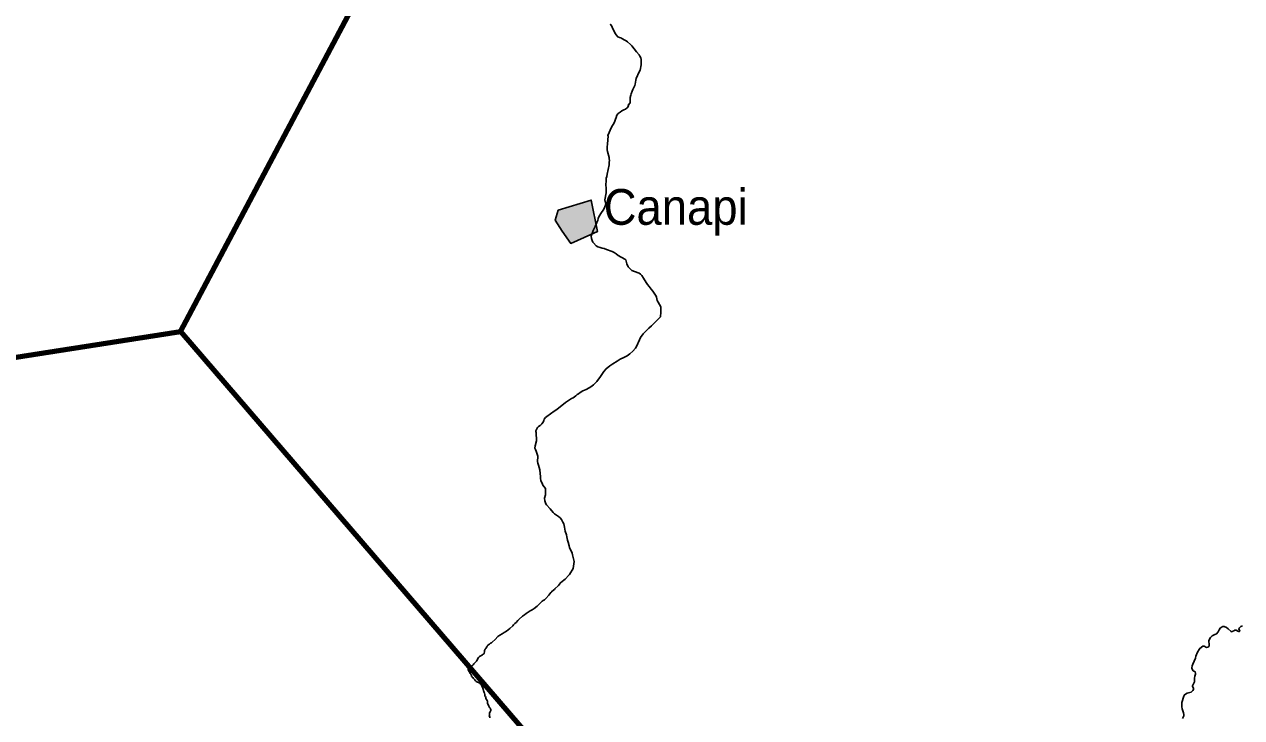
# Model space of a CAD drawing. Extents: x -1643653 to 4543381, y 1624270 to 13878484.
# Drawn here: x 644975 to 662004, y 8985110 to 8994810 of the extents above; entities that cross this region are included whole.
import ezdxf

# ---------------------------------------------------------------- set-up
doc = ezdxf.new("R2010")
doc.units = 0
doc.header["$LTSCALE"] = 200
for name, color, linetype, lineweight in [('21', 7, 'Continuous', 25), ('24', 7, 'Continuous', 25), ('60', 7, 'Continuous', 13), ('9', 7, 'Continuous', 90)]:
    doc.layers.add(name, color=color, linetype=linetype, lineweight=lineweight)
doc.layers.add('41', color=7, linetype='Continuous')

msp = doc.modelspace()

# ---------------------------------------------------------------- hatches: boundary and pattern name
at = {"layer": '21'}
msp.add_hatch(color=256, dxfattribs=at).paths.add_polyline_path([(652442.2, 8992209.7), (652905.2, 8992350.1), (652993.5, 8991912.7), (652618.8, 8991744.3), (652496.7, 8991914.1), (652399.6, 8992070.3)])

# ---------------------------------------------------------------- linework, layer by layer
msp.add_lwpolyline([(652442.2, 8992209.7), (652905.2, 8992350.1), (652993.5, 8991912.7), (652618.8, 8991744.3), (652496.7, 8991914.1), (652399.6, 8992070.3)], close=True, dxfattribs=at)
at = {"layer": '24'}
msp.add_line((651186.2, 8985771.9), (651204.8, 8985743), dxfattribs=at)
for points in [[(653170.7, 8994809.8), (653175.5, 8994807.6), (653191.3, 8994784), (653196.5, 8994768.7), (653211.1, 8994737.3), (653243.9, 8994674.7), (653252.4, 8994660.6), (653276.2, 8994633.6), (653299.1, 8994625.2), (653319.2, 8994620.5), (653334.8, 8994613.7), (653376.3, 8994588.9), (653394.7, 8994579.6), (653411.9, 8994563.4), (653455, 8994528.4), (653472.3, 8994508.8), (653537, 8994423.4), (653575.4, 8994381.7)], [(653575.4, 8994381.7), (653586.1, 8994365.1), (653599.4, 8994339.1), (653603.8, 8994319.8), (653604.9, 8994300.6), (653603.7, 8994242.8), (653588.1, 8994167.4), (653576.4, 8994144.9), (653533.3, 8994050.1), (653528, 8994030.9), (653518.3, 8993973.9), (653513.3, 8993955.5), (653488.2, 8993896.1), (653478.4, 8993876), (653466.1, 8993839), (653461.5, 8993819), (653450.8, 8993784.2), (653449.9, 8993778), (653451.5, 8993712.6), (653424.2, 8993677.3), (653424.4, 8993666.2), (653409.3, 8993643), (653384.1, 8993623.8), (653360.3, 8993615.7), (653334.2, 8993599.6), (653308, 8993581.4), (653282.8, 8993560), (653264.2, 8993540.2), (653251.9, 8993507.8), (653244.3, 8993482.9), (653237.7, 8993455.1), (653227.3, 8993430.2), (653188.7, 8993371.5), (653138.5, 8993253.8), (653138.8, 8993251.9), (653143, 8993247.7), (653131.9, 8993133.2)], [(653131.9, 8993133.2), (653129.8, 8993095.5), (653129.8, 8993054.8), (653132.2, 8993032.7), (653154.1, 8992948.6), (653155.5, 8992926.4), (653159.5, 8992905), (653155.4, 8992882), (653154.2, 8992844.1), (653130, 8992712), (653121.3, 8992682.4), (653116.5, 8992659.7), (653112.8, 8992631.9), (653112.8, 8992631.9), (653114.6, 8992605.4), (653111.6, 8992579.7), (653110.6, 8992554.8), (653113.8, 8992526.5), (653114.7, 8992476.9), (653112.5, 8992450.4), (653097.3, 8992353.7), (653111.6, 8992293.5), (653103.8, 8992279.2), (653085.8, 8992232.9), (653072.4, 8992208), (653050.1, 8992176.5), (653018, 8992124.4), (653004.3, 8992095.5), (652995.7, 8992065.1), (652985.9, 8992037.3), (652960.2, 8991981.7), (652933.3, 8991927.6), (652922.2, 8991899), (652906.4, 8991844.2), (652907.4, 8991815.5), (652917.9, 8991785.6), (652928.3, 8991762.9), (652936.6, 8991754.8), (652972.6, 8991709.8), (652998, 8991697.6), (653032.3, 8991688.1), (653060.2, 8991678.6), (653088, 8991673), (653117.6, 8991659.7), (653200.1, 8991632), (653227.9, 8991617), (653254.2, 8991600.8), (653281.5, 8991577.5), (653374.7, 8991524.4), (653387.3, 8991514.2), (653395.1, 8991496.5), (653404.1, 8991457.2), (653422.9, 8991419.4), (653438.6, 8991399.9), (653475.1, 8991367.3), (653508.4, 8991350.8), (653576.3, 8991330.8), (653594.5, 8991314.9), (653612.9, 8991293.9), (653637.5, 8991258.2), (653673.5, 8991199.1), (653693.7, 8991170.7), (653717.8, 8991140.5), (653744.1, 8991102.8), (653767.6, 8991074.9)], [(653767.6, 8991074.9), (653795.9, 8991037.1), (653814.2, 8991005.1), (653819.1, 8990993.8), (653828.8, 8990946.5), (653839.4, 8990921.2), (653878.5, 8990856.4), (653879.2, 8990781.4), (653873.4, 8990717.3), (653871, 8990712.8), (653853.9, 8990697.7), (653837.6, 8990680.5), (653785.8, 8990630.7), (653750.5, 8990593.4), (653711.8, 8990560), (653662.3, 8990513.6), (653630.7, 8990479.8), (653595.3, 8990428), (653578.7, 8990397.2), (653540.2, 8990301.5), (653523.5, 8990277.3), (653486.5, 8990235.3), (653446.5, 8990200.6), (653425.8, 8990184.6), (653406.2, 8990172.3), (653360.6, 8990147.5), (653312, 8990125.2), (653268.2, 8990099.5), (653207.5, 8990058.7), (653167.3, 8990033.5), (653113.8, 8989990.5), (653082.7, 8989954.3), (653036.6, 8989884.2), (652982.6, 8989813.8), (652936.7, 8989764.3), (652918.9, 8989751.1), (652899.7, 8989740.2)], [(652899.7, 8989740.2), (652877.8, 8989724.6), (652836.2, 8989703.3), (652811.9, 8989693.2), (652790, 8989682.3), (652749.2, 8989657.7), (652728.4, 8989641.9), (652709.2, 8989630), (652689.8, 8989614.1), (652651, 8989586.8), (652630, 8989575.5), (652587.2, 8989548.7), (652545.8, 8989519.3), (652446.2, 8989438), (652446.2, 8989438), (652410.2, 8989412.3), (652385.6, 8989397.2), (652285, 8989325.6), (652267.2, 8989307.9), (652248.4, 8989284.7), (652242.1, 8989265.4), (652232.1, 8989243.5), (652215.8, 8989220.3), (652206.6, 8989210.3), (652200.3, 8989208.7), (652190.4, 8989198.3), (652168.8, 8989181.8), (652154.9, 8989167.7), (652143.1, 8989149.5), (652131.2, 8989121), (652131.3, 8989114.2), (652134.5, 8989097.5), (652135.6, 8989052.2), (652139.7, 8989027.8), (652138.8, 8988983.3), (652120.9, 8988912.6), (652118.5, 8988880.4), (652123.9, 8988863.8), (652137.1, 8988840.6), (652156.5, 8988767.1), (652156.8, 8988741.8), (652151.8, 8988718.2), (652153.8, 8988694.7), (652158.1, 8988671.2), (652167.3, 8988644.8), (652184.8, 8988576.2), (652192.3, 8988528.1), (652195.3, 8988482.8), (652193.6, 8988458.5), (652201.4, 8988423.1), (652217.2, 8988390.3), (652226.7, 8988365.1), (652264.8, 8988314.8), (652267, 8988246.6), (652264.4, 8988229.4), (652253.4, 8988181), (652254.7, 8988143.9), (652270.8, 8988101.7), (652281, 8988087), (652329, 8988030.6), (652374.2, 8987979.9), (652391.1, 8987963.9), (652449.4, 8987924.6), (652469.8, 8987905.5), (652490.7, 8987881.2)], [(652490.7, 8987881.2), (652510.2, 8987846.4), (652519.9, 8987822.7), (652531.8, 8987775.1), (652540.2, 8987720.8), (652559.2, 8987669.4), (652563, 8987642), (652575.2, 8987593.2), (652584.9, 8987566.7), (652594.7, 8987515.3), (652603.6, 8987488.8), (652636.3, 8987409.7), (652643.8, 8987386.9), (652663.7, 8987311.6), (652665.1, 8987293.7), (652652.1, 8987197.7), (652601.8, 8987114.5), (652592.4, 8987105.1), (652542, 8987045.6), (652523, 8987034.7), (652498.3, 8987014.5), (652473.8, 8986997.1), (652445.6, 8986961.2), (652394.6, 8986912.1), (652389.2, 8986902.9), (652383.7, 8986900.8), (652349.6, 8986870.9), (652341.4, 8986859.7), (652310.3, 8986826.2), (652270.8, 8986778.6), (652249.9, 8986759.8), (652233.3, 8986751.7), (652218.9, 8986741.6), (652147.1, 8986669.5), (652105.7, 8986637.3), (652080.2, 8986619.2), (652052.1, 8986604.5)], [(652052.1, 8986604.5), (651993.9, 8986569.6), (651971.7, 8986550), (651946.1, 8986530.7), (651898, 8986488.9), (651877.6, 8986468.5), (651854.5, 8986442.5), (651837.6, 8986428.4), (651828.3, 8986417.3), (651817.8, 8986407.5), (651807.8, 8986394.7), (651766.1, 8986356.4), (651718, 8986321.2), (651688.2, 8986303.1), (651658.1, 8986282.5), (651658.1, 8986282.5), (651626.9, 8986265.4), (651599.8, 8986244.4), (651559.2, 8986206.1), (651520.7, 8986168.7)], [(661653.3, 8986283), (661653.3, 8986283), (661620.5, 8986267.7), (661592, 8986257.3), (661570, 8986232.2), (661542.9, 8986189), (661542.8, 8986172), (661548.9, 8986142.3), (661547.8, 8986116.5), (661542.4, 8986103.6), (661531.7, 8986095.3), (661511.3, 8986093.1), (661479.9, 8986111.5), (661462.2, 8986110.9), (661419.1, 8986079.2), (661409.3, 8986062.1), (661386.5, 8986028.5), (661363.9, 8985972.9), (661356, 8985944.3), (661319.8, 8985860.8), (661311.5, 8985833.8), (661305.7, 8985809), (661306.3, 8985803.2), (661316.7, 8985781.1), (661327.7, 8985766.6), (661351.7, 8985752.2), (661358.2, 8985733.2), (661356.2, 8985718.2), (661347.7, 8985689.5), (661343.3, 8985662.6), (661343.6, 8985612.7)], [(662016, 8986395.1), (661990.2, 8986386.8), (661968.5, 8986362.9), (661965.9, 8986353.2), (661971.2, 8986340.5), (661976, 8986334.1), (661975.9, 8986320.3), (661973.7, 8986317.5), (661968.6, 8986315), (661965.1, 8986315.2), (661950.7, 8986320.2), (661928.6, 8986334), (661912.3, 8986334.6), (661908.3, 8986333.7), (661893.5, 8986325.1), (661868.8, 8986314.5), (661859.1, 8986312.5), (661855.5, 8986314.2), (661815.1, 8986355.3), (661789.5, 8986371.6), (661760.9, 8986383.6), (661736.2, 8986383.9), (661731.5, 8986382.7), (661704.9, 8986363.8), (661689.3, 8986338.9), (661676.2, 8986309.1), (661653.3, 8986283)], [(651204.8, 8985743), (651207.2, 8985742), (651213.9, 8985728.9), (651219, 8985719.6), (651225.9, 8985710.1), (651228.7, 8985698.9), (651231.6, 8985688.2), (651238.7, 8985680.4), (651248, 8985669.9), (651257.4, 8985658.1), (651266.1, 8985646.8), (651274.7, 8985637.3), (651284.4, 8985627.7), (651295.8, 8985618.2), (651307, 8985610.1), (651316.5, 8985606.3), (651327.3, 8985603.1), (651336.7, 8985597), (651346.2, 8985589.2)], [(651346.2, 8985589.2), (651355, 8985581.5), (651363.6, 8985574.6), (651369.8, 8985565.8), (651376.3, 8985552.9), (651383.5, 8985538), (651388.5, 8985524.6), (651391.5, 8985509.8), (651393.7, 8985506.2), (651397.1, 8985496.6), (651400.3, 8985487), (651404.2, 8985474.3), (651408.3, 8985463), (651412.8, 8985452), (651418.7, 8985435.8), (651418.7, 8985424.8), (651417.8, 8985411.7), (651427.1, 8985404.6), (651431.1, 8985391.7), (651431, 8985378.3), (651438, 8985363.9), (651450, 8985349.8), (651452.6, 8985339), (651452.4, 8985326.2), (651455.9, 8985310.8), (651460.7, 8985300.5), (651467.1, 8985286.4), (651471.5, 8985272.6), (651480.6, 8985252), (651491.6, 8985241.3), (651498, 8985232.2), (651499.2, 8985221.1), (651498.6, 8985210.7), (651495.5, 8985199.1), (651489.9, 8985189.8), (651483.9, 8985177.2), (651482.7, 8985161.3), (651481.4, 8985151.4), (651479.7, 8985134), (651487.7, 8985121.6), (651487.9, 8985108.4)], [(661343.6, 8985612.7), (661317.2, 8985553.6), (661317.9, 8985549.5), (661330.3, 8985520.4), (661329.3, 8985505), (661322.5, 8985491.1), (661299.6, 8985468.5), (661239.9, 8985455.1), (661204.6, 8985431.5), (661193.6, 8985409.5), (661168.6, 8985320.2), (661165, 8985290.5), (661165.1, 8985261.8), (661169.5, 8985234.1), (661188.1, 8985180), (661194.4, 8985153.2), (661194.8, 8985134.1), (661192, 8985124.8), (661175.6, 8985097.4)]]:
    msp.add_lwpolyline(points, dxfattribs=at)
msp.add_spline([(651520.7, 8986168.7), (651496.7, 8986150.5), (651465.6, 8986128.3), (651437.7, 8986089.3), (651413.2, 8986049.2), (651407.7, 8986014.7), (651375.4, 8985983.5), (651318.6, 8985939), (651306.4, 8985912.2), (651265.2, 8985864.3), (651211.8, 8985817.6), (651197.3, 8985812), (651184, 8985788.6), (651186.8, 8985770.9)], degree=3, dxfattribs=at)
at = {"layer": '60', "lineweight": 25}
msp.add_spline([(814781, 9009175.5), (814787.2, 9009173.4), (814796.9, 9009173.4), (814799.4, 9009172.4), (814805.1, 9009174.5), (814805.6, 9009176.5), (814811.7, 9009179.5), (814811.7, 9009179.5), (814801.5, 9009181), (814790.7, 9009181.5), (814784.1, 9009183.1), (814777.4, 9009185.1), (814778.4, 9009175.5)], degree=3, dxfattribs=at)
at = {"layer": '9'}
msp.add_line((647160.3, 8990514), (659714.4, 8975927.2), dxfattribs=at)
msp.add_lwpolyline([(635350.7, 8977923.9), (636116.8, 8981777.4), (642228, 8989744.8), (647160.3, 8990514), (649828, 8995545.6), (655722.5, 9001435.5), (661506.7, 9009120.3)], dxfattribs=at)

# ---------------------------------------------------------------- texts
at = {"layer": '41', "width": 0.95}
msp.add_text('Canapi', height=500, dxfattribs=at).set_placement((653080.1, 8992005.4))

doc.saveas('drawing.dxf')
